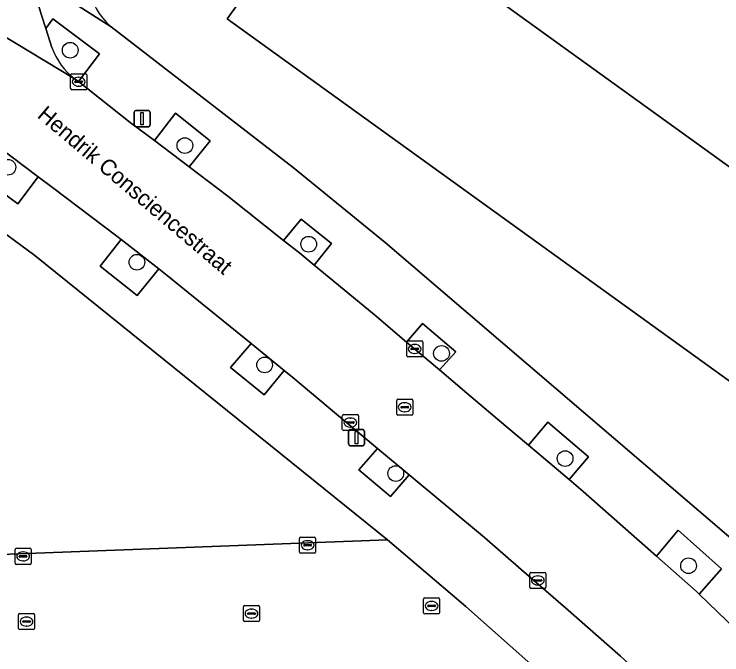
# Model space of a CAD drawing. Extents: x 160349 to 161355, y 381727 to 382854.
# Drawn here: x 160924.36 to 160968.51, y 382053.69 to 382093.63 of the extents above; entities that cross this region are included whole.
import ezdxf

# ---------------------------------------------------------------- set-up
doc = ezdxf.new("R2010")
doc.units = 0
for name, color, linetype in [('IMGEO_Boom', 7, 'Continuous'), ('IMGEO_Erf', 7, 'Continuous'), ('IMGEO_Groenvoorziening', 7, 'Continuous'), ('IMGEO_Kolk', 7, 'Continuous'), ('IMGEO_Lichtmast', 7, 'Continuous'), ('IMGEO_Openbare_ruimte_label', 7, 'Continuous'), ('IMGEO_Pand', 7, 'Continuous'), ('IMGEO_Rijbaan_lokaal_open', 7, 'Continuous'), ('IMGEO_Rioolput', 7, 'Continuous'), ('IMGEO_Voetpad_open', 7, 'Continuous')]:
    doc.layers.add(name, color=color, linetype=linetype)

msp = doc.modelspace()

# ---------------------------------------------------------------- linework, layer by layer
at = {"layer": 'IMGEO_Boom'}
for centre in [(160927.858, 382091.386), (160935.011, 382085.44), (160923.978, 382084.088), (160942.736, 382079.29), (160932.021, 382078.167), (160951.019, 382072.48), (160939.986, 382071.763), (160958.73, 382065.924), (160948.168, 382064.991), (160966.429, 382059.24)]:
    msp.add_circle(centre, 0.489, dxfattribs=at)
at = {"layer": 'IMGEO_Erf'}
msp.add_lwpolyline([(160974.75, 382079.961), (160980.406, 382087.807), (160976.479, 382090.639), (160982.169, 382098.533), (160986.073, 382095.72), (160991.577, 382103.356), (160960.839, 382125.613), (160967.371, 382134.674), (160981.032, 382124.828), (160981.957, 382124.161), (161000, 382111.157), (161006.438, 382106.555), (161000, 382097.624), (160976.649, 382065.23), (160937.66, 382093.334), (160943.998, 382102.128)], close=True, dxfattribs=at)
msp.add_lwpolyline([(160930.416, 382092.841), (160941.771, 382084.079), (160947.496, 382079.387), (160970.663, 382059.599)], dxfattribs=at)
msp.add_arc((160933.019, 382095.929), 4.039, 146.2871, 229.8798, dxfattribs=at)
at = {"layer": 'IMGEO_Groenvoorziening'}
for points in [[(160928.172, 382089.588), (160928.369, 382089.433), (160929.696, 382091.154), (160926.773, 382093.348), (160926.341, 382092.737)], [(160926.341, 382092.737), (160926.722, 382091.56)], [(160925.653, 382078.584), (160913.903, 382087.23)], [(160920.227, 382059.811), (160947.65, 382060.865), (160925.653, 382078.584)]]:
    msp.add_lwpolyline(points, dxfattribs=at)
for points in [[(160933.107, 382085.748), (160935.28, 382084.105), (160936.581, 382085.731), (160934.417, 382087.451)], [(160923.287, 382085.428), (160922.016, 382083.695), (160924.595, 382081.816), (160925.851, 382083.501)], [(160941.168, 382079.528), (160942.183, 382078.724), (160943.071, 382077.993), (160944.151, 382079.324), (160942.266, 382080.848)], [(160931.044, 382079.583), (160929.731, 382077.92), (160932.027, 382076.1), (160933.378, 382077.748)], [(160948.845, 382073.185), (160950.886, 382071.45), (160951.918, 382072.588), (160949.839, 382074.354)], [(160939.141, 382073.105), (160937.861, 382071.596), (160939.968, 382069.893), (160941.204, 382071.413)], [(160956.436, 382066.753), (160958.972, 382064.616), (160960.192, 382066.042), (160957.645, 382068.198)], [(160947.033, 382066.558), (160945.867, 382065.215), (160947.848, 382063.557), (160949.002, 382064.915)], [(160964.421, 382059.843), (160966.911, 382057.646), (160967.099, 382057.466), (160968.482, 382059.048), (160965.789, 382061.464)]]:
    msp.add_lwpolyline(points, close=True, dxfattribs=at)
msp.add_arc((160930.591, 382092.886), 4.09, 198.9147, 233.7389, dxfattribs=at)
at = {"layer": 'IMGEO_Kolk'}
for p, q in [((160927.887, 382088.993), (160927.887, 382089.845)), ((160927.962, 382089.919), (160928.814, 382089.919)), ((160928.888, 382089.845), (160928.888, 382088.993)), ((160928.146, 382089.413), (160928.146, 382089.425)), ((160928.584, 382089.376), (160928.186, 382089.376)), ((160928.189, 382089.462), (160928.587, 382089.462)), ((160928.375, 382089.699), (160928.4, 382089.699)), ((160928.63, 382089.425), (160928.63, 382089.413)), ((160928.398, 382089.139), (160928.373, 382089.139)), ((160928.814, 382088.919), (160927.962, 382088.919)), ((160948.847, 382072.333), (160948.847, 382073.185)), ((160948.922, 382073.259), (160949.774, 382073.259)), ((160949.335, 382073.039), (160949.36, 382073.039)), ((160949.848, 382073.185), (160949.848, 382072.333)), ((160949.106, 382072.753), (160949.106, 382072.765)), ((160949.544, 382072.716), (160949.146, 382072.716)), ((160949.149, 382072.802), (160949.547, 382072.802)), ((160949.59, 382072.765), (160949.59, 382072.753)), ((160949.774, 382072.259), (160948.922, 382072.259)), ((160949.358, 382072.479), (160949.333, 382072.479)), ((160944.908, 382068.671), (160945.76, 382068.671)), ((160944.833, 382067.745), (160944.833, 382068.597)), ((160945.135, 382068.214), (160945.533, 382068.214)), ((160945.321, 382068.451), (160945.346, 382068.451)), ((160945.834, 382068.597), (160945.834, 382067.745)), ((160945.092, 382068.165), (160945.092, 382068.177)), ((160945.53, 382068.128), (160945.132, 382068.128)), ((160945.344, 382067.891), (160945.319, 382067.891)), ((160945.576, 382068.177), (160945.576, 382068.165)), ((160945.76, 382067.671), (160944.908, 382067.671)), ((160942.167, 382060.097), (160942.167, 382060.949)), ((160942.242, 382061.023), (160943.094, 382061.023)), ((160942.655, 382060.803), (160942.68, 382060.803)), ((160943.168, 382060.949), (160943.168, 382060.097)), ((160924.421, 382059.401), (160924.421, 382060.253)), ((160924.496, 382060.327), (160925.348, 382060.327)), ((160925.422, 382060.253), (160925.422, 382059.401)), ((160942.426, 382060.517), (160942.426, 382060.529)), ((160942.864, 382060.48), (160942.466, 382060.48)), ((160942.469, 382060.566), (160942.867, 382060.566)), ((160942.678, 382060.243), (160942.653, 382060.243)), ((160942.91, 382060.529), (160942.91, 382060.517)), ((160924.68, 382059.821), (160924.68, 382059.833)), ((160924.723, 382059.87), (160925.121, 382059.87)), ((160924.909, 382060.107), (160924.934, 382060.107)), ((160925.164, 382059.833), (160925.164, 382059.821)), ((160943.094, 382060.023), (160942.242, 382060.023)), ((160925.118, 382059.784), (160924.72, 382059.784)), ((160924.932, 382059.547), (160924.907, 382059.547)), ((160925.348, 382059.327), (160924.496, 382059.327)), ((160956.526, 382057.902), (160956.526, 382058.754)), ((160956.601, 382058.828), (160957.453, 382058.828)), ((160957.014, 382058.608), (160957.039, 382058.608)), ((160957.527, 382058.754), (160957.527, 382057.902)), ((160956.785, 382058.322), (160956.785, 382058.334)), ((160957.223, 382058.285), (160956.825, 382058.285)), ((160956.828, 382058.371), (160957.226, 382058.371)), ((160957.037, 382058.048), (160957.012, 382058.048)), ((160957.269, 382058.334), (160957.269, 382058.322)), ((160957.453, 382057.828), (160956.601, 382057.828)), ((160949.902, 382056.309), (160949.902, 382057.161)), ((160949.977, 382057.235), (160950.829, 382057.235)), ((160950.903, 382057.161), (160950.903, 382056.309)), ((160938.741, 382056.758), (160939.593, 382056.758)), ((160950.161, 382056.729), (160950.161, 382056.741)), ((160950.204, 382056.778), (160950.602, 382056.778)), ((160950.39, 382057.015), (160950.415, 382057.015)), ((160950.645, 382056.741), (160950.645, 382056.729)), ((160938.666, 382055.832), (160938.666, 382056.684)), ((160938.925, 382056.252), (160938.925, 382056.264)), ((160938.968, 382056.301), (160939.366, 382056.301)), ((160939.154, 382056.538), (160939.179, 382056.538)), ((160939.409, 382056.264), (160939.409, 382056.252)), ((160939.667, 382056.684), (160939.667, 382055.832)), ((160950.599, 382056.692), (160950.201, 382056.692)), ((160950.413, 382056.455), (160950.388, 382056.455)), ((160924.636, 382055.333), (160924.636, 382056.185)), ((160924.711, 382056.259), (160925.563, 382056.259)), ((160925.124, 382056.039), (160925.149, 382056.039)), ((160925.637, 382056.185), (160925.637, 382055.333)), ((160939.363, 382056.215), (160938.965, 382056.215)), ((160939.177, 382055.978), (160939.152, 382055.978)), ((160950.829, 382056.235), (160949.977, 382056.235)), ((160924.895, 382055.753), (160924.895, 382055.765)), ((160925.333, 382055.716), (160924.935, 382055.716)), ((160924.938, 382055.802), (160925.336, 382055.802)), ((160925.147, 382055.479), (160925.122, 382055.479)), ((160925.379, 382055.765), (160925.379, 382055.753)), ((160939.593, 382055.758), (160938.741, 382055.758)), ((160925.563, 382055.259), (160924.711, 382055.259))]:
    msp.add_line(p, q, dxfattribs=at)
for points in [[(160927.887, 382088.993), (160927.887, 382089.845)], [(160927.962, 382089.919), (160928.814, 382089.919)], [(160928.888, 382089.845), (160928.888, 382088.993)], [(160928.814, 382088.919), (160927.962, 382088.919)], [(160948.847, 382072.333), (160948.847, 382073.185)], [(160948.922, 382073.259), (160949.774, 382073.259)], [(160949.848, 382073.185), (160949.848, 382072.333)], [(160949.774, 382072.259), (160948.922, 382072.259)], [(160944.908, 382068.671), (160945.76, 382068.671)], [(160944.833, 382067.745), (160944.833, 382068.597)], [(160945.834, 382068.597), (160945.834, 382067.745)], [(160945.76, 382067.671), (160944.908, 382067.671)], [(160942.167, 382060.097), (160942.167, 382060.949)], [(160942.242, 382061.023), (160943.094, 382061.023)], [(160943.168, 382060.949), (160943.168, 382060.097)], [(160924.421, 382059.401), (160924.421, 382060.253)], [(160924.496, 382060.327), (160925.348, 382060.327)], [(160925.422, 382060.253), (160925.422, 382059.401)], [(160943.094, 382060.023), (160942.242, 382060.023)], [(160925.348, 382059.327), (160924.496, 382059.327)], [(160956.526, 382057.902), (160956.526, 382058.754)], [(160956.601, 382058.828), (160957.453, 382058.828)], [(160957.527, 382058.754), (160957.527, 382057.902)], [(160957.453, 382057.828), (160956.601, 382057.828)], [(160949.902, 382056.309), (160949.902, 382057.161)], [(160949.977, 382057.235), (160950.829, 382057.235)], [(160950.903, 382057.161), (160950.903, 382056.309)], [(160938.741, 382056.758), (160939.593, 382056.758)], [(160938.666, 382055.832), (160938.666, 382056.684)], [(160939.667, 382056.684), (160939.667, 382055.832)], [(160924.636, 382055.333), (160924.636, 382056.185)], [(160924.711, 382056.259), (160925.563, 382056.259)], [(160925.637, 382056.185), (160925.637, 382055.333)], [(160950.829, 382056.235), (160949.977, 382056.235)], [(160939.593, 382055.758), (160938.741, 382055.758)], [(160925.563, 382055.259), (160924.711, 382055.259)]]:
    msp.add_lwpolyline(points, dxfattribs=at)
for centre, radius, start, end in [((160927.964, 382089.843), 0.0765, 91.552, 178.448), ((160927.964, 382089.843), 0.0765, 91.552, 178.448), ((160928.812, 382089.843), 0.0765, 1.552, 88.448), ((160928.812, 382089.843), 0.0765, 1.552, 88.448), ((160928.186, 382089.422), 0.0403, 85.8775, 175.7526), ((160928.183, 382089.412), 0.0366, 178.938, 274.7102), ((160928.587, 382089.419), 0.043, 264.8664, 352.4533), ((160928.591, 382089.424), 0.0386, 1.7309, 96.639), ((160927.964, 382088.995), 0.0765, 181.552, 268.448), ((160927.964, 382088.995), 0.0765, 181.552, 268.448), ((160928.812, 382088.995), 0.0765, 271.552, 358.448), ((160928.812, 382088.995), 0.0765, 271.552, 358.448), ((160948.924, 382073.183), 0.0765, 91.552, 178.448), ((160948.924, 382073.183), 0.0765, 91.552, 178.448), ((160949.772, 382073.183), 0.0765, 1.552, 88.448), ((160949.772, 382073.183), 0.0765, 1.552, 88.448), ((160949.146, 382072.762), 0.0403, 85.8775, 175.7526), ((160949.143, 382072.752), 0.0366, 178.938, 274.7102), ((160949.547, 382072.759), 0.043, 264.8664, 352.4533), ((160949.551, 382072.764), 0.0386, 1.7309, 96.639), ((160948.924, 382072.335), 0.0765, 181.552, 268.448), ((160948.924, 382072.335), 0.0765, 181.552, 268.448), ((160949.772, 382072.335), 0.0765, 271.552, 358.448), ((160949.772, 382072.335), 0.0765, 271.552, 358.448), ((160944.91, 382068.595), 0.0765, 91.552, 178.448), ((160944.91, 382068.595), 0.0765, 91.552, 178.448), ((160945.758, 382068.595), 0.0765, 1.552, 88.448), ((160945.758, 382068.595), 0.0765, 1.552, 88.448), ((160945.132, 382068.174), 0.0403, 85.8775, 175.7526), ((160945.537, 382068.176), 0.0386, 1.7309, 96.639), ((160944.91, 382067.747), 0.0765, 181.552, 268.448), ((160944.91, 382067.747), 0.0765, 181.552, 268.448), ((160945.129, 382068.164), 0.0366, 178.938, 274.7102), ((160945.533, 382068.171), 0.043, 264.8664, 352.4533), ((160945.758, 382067.747), 0.0765, 271.552, 358.448), ((160945.758, 382067.747), 0.0765, 271.552, 358.448), ((160942.244, 382060.947), 0.0765, 91.552, 178.448), ((160942.244, 382060.947), 0.0765, 91.552, 178.448), ((160943.092, 382060.947), 0.0765, 1.552, 88.448), ((160943.092, 382060.947), 0.0765, 1.552, 88.448), ((160924.498, 382060.251), 0.0765, 91.552, 178.448), ((160924.498, 382060.251), 0.0765, 91.552, 178.448), ((160925.346, 382060.251), 0.0765, 1.552, 88.448), ((160925.346, 382060.251), 0.0765, 1.552, 88.448), ((160942.466, 382060.526), 0.0403, 85.8775, 175.7526), ((160942.463, 382060.516), 0.0366, 178.938, 274.7102), ((160942.867, 382060.523), 0.043, 264.8664, 352.4533), ((160942.871, 382060.528), 0.0386, 1.7309, 96.639), ((160924.72, 382059.83), 0.0403, 85.8775, 175.7526), ((160924.717, 382059.82), 0.0366, 178.938, 274.7102), ((160925.121, 382059.827), 0.043, 264.8664, 352.4533), ((160925.125, 382059.832), 0.0386, 1.7309, 96.639), ((160942.244, 382060.099), 0.0765, 181.552, 268.448), ((160942.244, 382060.099), 0.0765, 181.552, 268.448), ((160943.092, 382060.099), 0.0765, 271.552, 358.448), ((160943.092, 382060.099), 0.0765, 271.552, 358.448), ((160924.498, 382059.403), 0.0765, 181.552, 268.448), ((160924.498, 382059.403), 0.0765, 181.552, 268.448), ((160925.346, 382059.403), 0.0765, 271.552, 358.448), ((160925.346, 382059.403), 0.0765, 271.552, 358.448), ((160956.603, 382058.752), 0.0765, 91.552, 178.448), ((160956.603, 382058.752), 0.0765, 91.552, 178.448), ((160957.451, 382058.752), 0.0765, 1.552, 88.448), ((160957.451, 382058.752), 0.0765, 1.552, 88.448), ((160956.825, 382058.331), 0.0403, 85.8775, 175.7526), ((160956.822, 382058.321), 0.0366, 178.938, 274.7102), ((160957.226, 382058.328), 0.043, 264.8664, 352.4533), ((160957.23, 382058.333), 0.0386, 1.7309, 96.639), ((160956.603, 382057.904), 0.0765, 181.552, 268.448), ((160956.603, 382057.904), 0.0765, 181.552, 268.448), ((160957.451, 382057.904), 0.0765, 271.552, 358.448), ((160957.451, 382057.904), 0.0765, 271.552, 358.448), ((160949.979, 382057.159), 0.0765, 91.552, 178.448), ((160949.979, 382057.159), 0.0765, 91.552, 178.448), ((160950.827, 382057.159), 0.0765, 1.552, 88.448), ((160950.827, 382057.159), 0.0765, 1.552, 88.448), ((160938.743, 382056.682), 0.0765, 91.552, 178.448), ((160938.743, 382056.682), 0.0765, 91.552, 178.448), ((160939.591, 382056.682), 0.0765, 1.552, 88.448), ((160939.591, 382056.682), 0.0765, 1.552, 88.448), ((160950.201, 382056.738), 0.0403, 85.8775, 175.7526), ((160950.198, 382056.728), 0.0366, 178.938, 274.7102), ((160950.602, 382056.735), 0.043, 264.8664, 352.4533), ((160950.606, 382056.74), 0.0386, 1.7309, 96.639), ((160938.965, 382056.261), 0.0403, 85.8775, 175.7526), ((160939.37, 382056.263), 0.0386, 1.7309, 96.639), ((160949.979, 382056.311), 0.0765, 181.552, 268.448), ((160949.979, 382056.311), 0.0765, 181.552, 268.448), ((160950.827, 382056.311), 0.0765, 271.552, 358.448), ((160950.827, 382056.311), 0.0765, 271.552, 358.448), ((160924.713, 382056.183), 0.0765, 91.552, 178.448), ((160924.713, 382056.183), 0.0765, 91.552, 178.448), ((160925.561, 382056.183), 0.0765, 1.552, 88.448), ((160925.561, 382056.183), 0.0765, 1.552, 88.448), ((160938.743, 382055.834), 0.0765, 181.552, 268.448), ((160938.743, 382055.834), 0.0765, 181.552, 268.448), ((160938.962, 382056.251), 0.0366, 178.938, 274.7102), ((160939.366, 382056.258), 0.043, 264.8664, 352.4533), ((160939.591, 382055.834), 0.0765, 271.552, 358.448), ((160939.591, 382055.834), 0.0765, 271.552, 358.448), ((160924.935, 382055.762), 0.0403, 85.8775, 175.7526), ((160924.932, 382055.752), 0.0366, 178.938, 274.7102), ((160925.336, 382055.759), 0.043, 264.8664, 352.4533), ((160925.34, 382055.764), 0.0386, 1.7309, 96.639), ((160924.713, 382055.335), 0.0765, 181.552, 268.448), ((160924.713, 382055.335), 0.0765, 181.552, 268.448), ((160925.561, 382055.335), 0.0765, 271.552, 358.448), ((160925.561, 382055.335), 0.0765, 271.552, 358.448)]:
    msp.add_arc(centre, radius, start, end, dxfattribs=at)
for centre, major_axis, ratio, start_param, end_param in [((160928.374, 382089.419), (-0.387, 0.002), 0.722429, 4.712389, 7.853982), ((160928.399, 382089.419), (-0.39, 0.002), 0.717154, 1.570796, 4.712389), ((160949.334, 382072.759), (-0.387, 0.002), 0.722429, 4.712389, 7.853982), ((160949.359, 382072.759), (-0.39, 0.002), 0.717154, 1.570796, 4.712389), ((160945.32, 382068.171), (-0.387, 0.002), 0.722429, 4.712389, 7.853982), ((160945.345, 382068.171), (-0.39, 0.002), 0.717154, 1.570796, 4.712389), ((160942.654, 382060.523), (-0.387, 0.002), 0.722429, 4.712389, 7.853982), ((160942.679, 382060.523), (-0.39, 0.002), 0.717154, 1.570796, 4.712389), ((160924.908, 382059.827), (-0.387, 0.002), 0.722429, 4.712389, 7.853982), ((160924.933, 382059.827), (-0.39, 0.002), 0.717154, 1.570796, 4.712389), ((160957.013, 382058.328), (-0.387, 0.002), 0.722429, 4.712389, 7.853982), ((160957.038, 382058.328), (-0.39, 0.002), 0.717154, 1.570796, 4.712389), ((160950.389, 382056.735), (-0.387, 0.002), 0.722429, 4.712389, 7.853982), ((160950.414, 382056.735), (-0.39, 0.002), 0.717154, 1.570796, 4.712389), ((160939.153, 382056.258), (-0.387, 0.002), 0.722429, 4.712389, 7.853982), ((160939.178, 382056.258), (-0.39, 0.002), 0.717154, 1.570796, 4.712389), ((160925.123, 382055.759), (-0.387, 0.002), 0.722429, 4.712389, 7.853982), ((160925.148, 382055.759), (-0.39, 0.002), 0.717154, 1.570796, 4.712389)]:
    msp.add_ellipse(centre, major_axis=major_axis, ratio=ratio, start_param=start_param, end_param=end_param, dxfattribs=at)
at = {"layer": 'IMGEO_Lichtmast'}
for p, q in [((160931.948, 382087.617), (160932.738, 382087.617)), ((160932.738, 382087.617), (160931.948, 382087.617)), ((160931.848, 382086.717), (160931.848, 382087.517)), ((160931.848, 382087.517), (160931.848, 382086.717)), ((160932.838, 382087.517), (160932.838, 382086.717)), ((160932.838, 382086.717), (160932.838, 382087.517)), ((160932.738, 382086.617), (160931.948, 382086.617)), ((160931.948, 382086.617), (160932.738, 382086.617)), ((160945.221, 382066.827), (160945.221, 382067.627)), ((160945.221, 382067.627), (160945.221, 382066.827)), ((160945.321, 382067.727), (160946.111, 382067.727)), ((160946.111, 382067.727), (160945.321, 382067.727)), ((160946.211, 382067.627), (160946.211, 382066.827)), ((160946.211, 382066.827), (160946.211, 382067.627)), ((160946.111, 382066.727), (160945.321, 382066.727)), ((160945.321, 382066.727), (160946.111, 382066.727))]:
    msp.add_line(p, q, dxfattribs=at)
for points in [[(160932.268, 382087.492), (160932.418, 382087.492), (160932.418, 382086.742), (160932.268, 382086.742), (160932.268, 382087.492)], [(160945.641, 382067.602), (160945.791, 382067.602), (160945.791, 382066.852), (160945.641, 382066.852), (160945.641, 382067.602)]]:
    msp.add_lwpolyline(points, dxfattribs=at)
for centre, start, end in [((160931.948, 382087.517), 90, 180), ((160931.948, 382087.517), 90, 180), ((160932.738, 382087.517), 0, 90), ((160932.738, 382087.517), 360, 90), ((160931.948, 382086.717), 180, 270), ((160931.948, 382086.717), 180, 270), ((160932.738, 382086.717), 270, 0), ((160932.738, 382086.717), 270, 0), ((160945.321, 382067.627), 90, 180), ((160945.321, 382067.627), 90, 180), ((160946.111, 382067.627), 0, 90), ((160946.111, 382067.627), 360, 90), ((160945.321, 382066.827), 180, 270), ((160945.321, 382066.827), 180, 270), ((160946.111, 382066.827), 270, 0), ((160946.111, 382066.827), 270, 0)]:
    msp.add_arc(centre, 0.1, start, end, dxfattribs=at)
at = {"layer": 'IMGEO_Pand'}
msp.add_lwpolyline([(160981.957, 382124.161), (160981.032, 382124.828), (160967.371, 382134.674), (160960.839, 382125.613), (160991.577, 382103.356), (160986.073, 382095.72), (160982.169, 382098.533), (160976.479, 382090.639), (160980.406, 382087.807), (160974.75, 382079.961), (160943.998, 382102.128), (160937.66, 382093.334), (160976.649, 382065.23), (161000, 382097.624), (161006.438, 382106.555), (161000, 382111.157)], close=True, dxfattribs=at)
at = {"layer": 'IMGEO_Rijbaan_lokaal_open'}
for points in [[(160970.531, 382054.167), (160967.099, 382057.466), (160966.911, 382057.646), (160964.421, 382059.843), (160959.865, 382063.864), (160958.972, 382064.616), (160956.436, 382066.753), (160955.024, 382067.943), (160952.589, 382070.002), (160950.886, 382071.45), (160948.845, 382073.185), (160946.812, 382074.914), (160943.071, 382077.993), (160942.183, 382078.724), (160941.168, 382079.528), (160937.686, 382082.286), (160935.28, 382084.105), (160933.107, 382085.748), (160931.597, 382086.889), (160928.369, 382089.433), (160928.172, 382089.588), (160912.113, 382099.295)], [(160912.113, 382099.295), (160928.172, 382089.588)], [(160926.722, 382091.56), (160926.341, 382092.737), (160926.052, 382093.631), (160925.737, 382094.705), (160925.379, 382096.066)], [(160923.287, 382085.428), (160925.851, 382083.501), (160926.75, 382082.826), (160930.773, 382079.796), (160931.044, 382079.583), (160933.378, 382077.748), (160933.9, 382077.338), (160938.279, 382073.812), (160939.141, 382073.105), (160941.204, 382071.413), (160941.742, 382070.971), (160944.988, 382068.265), (160947.033, 382066.558), (160949.002, 382064.915), (160953.698, 382060.997), (160955.988, 382059.014), (160958.753, 382056.615), (160962.177, 382053.605), (160962.709, 382053.131), (160964.06, 382051.926), (160964.292, 382051.719), (160966.468, 382049.768), (160967.756, 382048.614), (160968.542, 382047.88)]]:
    msp.add_lwpolyline(points, dxfattribs=at)
msp.add_arc((160930.591, 382092.886), 4.09, 198.9147, 233.7389, dxfattribs=at)
at = {"layer": 'IMGEO_Rioolput'}
for p, q in [((160948.225, 382068.7), (160948.225, 382069.552)), ((160948.3, 382069.626), (160949.152, 382069.626)), ((160949.226, 382069.552), (160949.226, 382068.7)), ((160948.484, 382069.12), (160948.484, 382069.132)), ((160948.922, 382069.083), (160948.524, 382069.083)), ((160948.527, 382069.169), (160948.925, 382069.169)), ((160948.713, 382069.406), (160948.738, 382069.406)), ((160948.968, 382069.132), (160948.968, 382069.12)), ((160949.152, 382068.626), (160948.3, 382068.626)), ((160948.736, 382068.846), (160948.711, 382068.846))]:
    msp.add_line(p, q, dxfattribs=at)
for points in [[(160948.225, 382068.7), (160948.225, 382069.552)], [(160948.3, 382069.626), (160949.152, 382069.626)], [(160949.226, 382069.552), (160949.226, 382068.7)], [(160949.152, 382068.626), (160948.3, 382068.626)]]:
    msp.add_lwpolyline(points, dxfattribs=at)
for centre, radius, start, end in [((160948.302, 382069.55), 0.0765, 91.552, 178.448), ((160948.302, 382069.55), 0.0765, 91.552, 178.448), ((160949.15, 382069.55), 0.0765, 1.552, 88.448), ((160949.15, 382069.55), 0.0765, 1.552, 88.448), ((160948.524, 382069.129), 0.0403, 85.8775, 175.7526), ((160948.521, 382069.119), 0.0366, 178.938, 274.7102), ((160948.925, 382069.126), 0.043, 264.8664, 352.4533), ((160948.929, 382069.131), 0.0386, 1.7309, 96.639), ((160948.302, 382068.702), 0.0765, 181.552, 268.448), ((160948.302, 382068.702), 0.0765, 181.552, 268.448), ((160949.15, 382068.702), 0.0765, 271.552, 358.448), ((160949.15, 382068.702), 0.0765, 271.552, 358.448)]:
    msp.add_arc(centre, radius, start, end, dxfattribs=at)
for centre, major_axis, ratio, start_param, end_param in [((160948.712, 382069.126), (-0.387, 0.002), 0.722429, 4.712389, 7.853982), ((160948.737, 382069.126), (-0.39, 0.002), 0.717154, 1.570796, 4.712389)]:
    msp.add_ellipse(centre, major_axis=major_axis, ratio=ratio, start_param=start_param, end_param=end_param, dxfattribs=at)
at = {"layer": 'IMGEO_Voetpad_open'}
for points in [[(160925.379, 382096.066), (160930.416, 382092.841)], [(160947.496, 382079.387), (160941.771, 382084.079), (160930.416, 382092.841), (160925.379, 382096.066)], [(160925.737, 382094.705), (160926.052, 382093.631), (160926.341, 382092.737), (160926.773, 382093.348), (160929.696, 382091.154), (160928.369, 382089.433), (160931.597, 382086.889), (160933.107, 382085.748), (160934.417, 382087.451), (160936.581, 382085.731), (160935.28, 382084.105), (160937.686, 382082.286), (160941.168, 382079.528), (160942.266, 382080.848), (160944.151, 382079.324), (160943.071, 382077.993), (160946.812, 382074.914), (160948.845, 382073.185), (160949.839, 382074.354), (160951.918, 382072.588), (160950.886, 382071.45), (160952.589, 382070.002), (160955.024, 382067.943), (160956.436, 382066.753), (160957.645, 382068.198), (160960.192, 382066.042), (160958.972, 382064.616), (160959.865, 382063.864), (160964.421, 382059.843), (160965.789, 382061.464), (160968.482, 382059.048), (160967.099, 382057.466), (160970.531, 382054.167)], [(160939.141, 382073.105), (160938.279, 382073.812), (160933.9, 382077.338), (160933.378, 382077.748), (160932.027, 382076.1), (160929.731, 382077.92), (160931.044, 382079.583), (160930.773, 382079.796), (160926.75, 382082.826), (160925.851, 382083.501), (160924.595, 382081.816), (160922.016, 382083.695), (160923.287, 382085.428), (160922.706, 382085.864), (160918.653, 382088.794), (160917.389, 382087.058), (160914.132, 382089.263), (160915.368, 382090.978), (160913.578, 382092.049)], [(160913.903, 382087.23), (160925.653, 382078.584), (160947.65, 382060.865), (160952.547, 382056.706), (160961.02, 382049.177)], [(160970.663, 382059.599), (160947.496, 382079.387)], [(160961.811, 382044.304), (160966.468, 382049.768), (160964.292, 382051.719), (160964.06, 382051.926), (160962.879, 382050.517), (160961.466, 382051.644), (160962.709, 382053.131), (160962.177, 382053.605), (160958.753, 382056.615), (160955.988, 382059.014), (160953.698, 382060.997), (160949.002, 382064.915), (160947.848, 382063.557), (160945.867, 382065.215), (160947.033, 382066.558), (160944.988, 382068.265), (160941.742, 382070.971), (160941.204, 382071.413), (160939.968, 382069.893), (160937.861, 382071.596), (160939.141, 382073.105)], [(160952.547, 382056.706), (160947.65, 382060.865), (160920.227, 382059.811)], [(160961.02, 382049.177), (160952.547, 382056.706)]]:
    msp.add_lwpolyline(points, dxfattribs=at)
msp.add_arc((160933.019, 382095.929), 4.039, 146.2871, 229.8798, dxfattribs=at)

# ---------------------------------------------------------------- texts
at = {"layer": 'IMGEO_Openbare_ruimte_label'}
msp.add_text('Hendrik Consciencestraat', height=1, rotation=319.7468, dxfattribs=at).set_placement((160925.744, 382087.236))

doc.saveas('drawing.dxf')
